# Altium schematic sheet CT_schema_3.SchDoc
size 313 x 200 mm
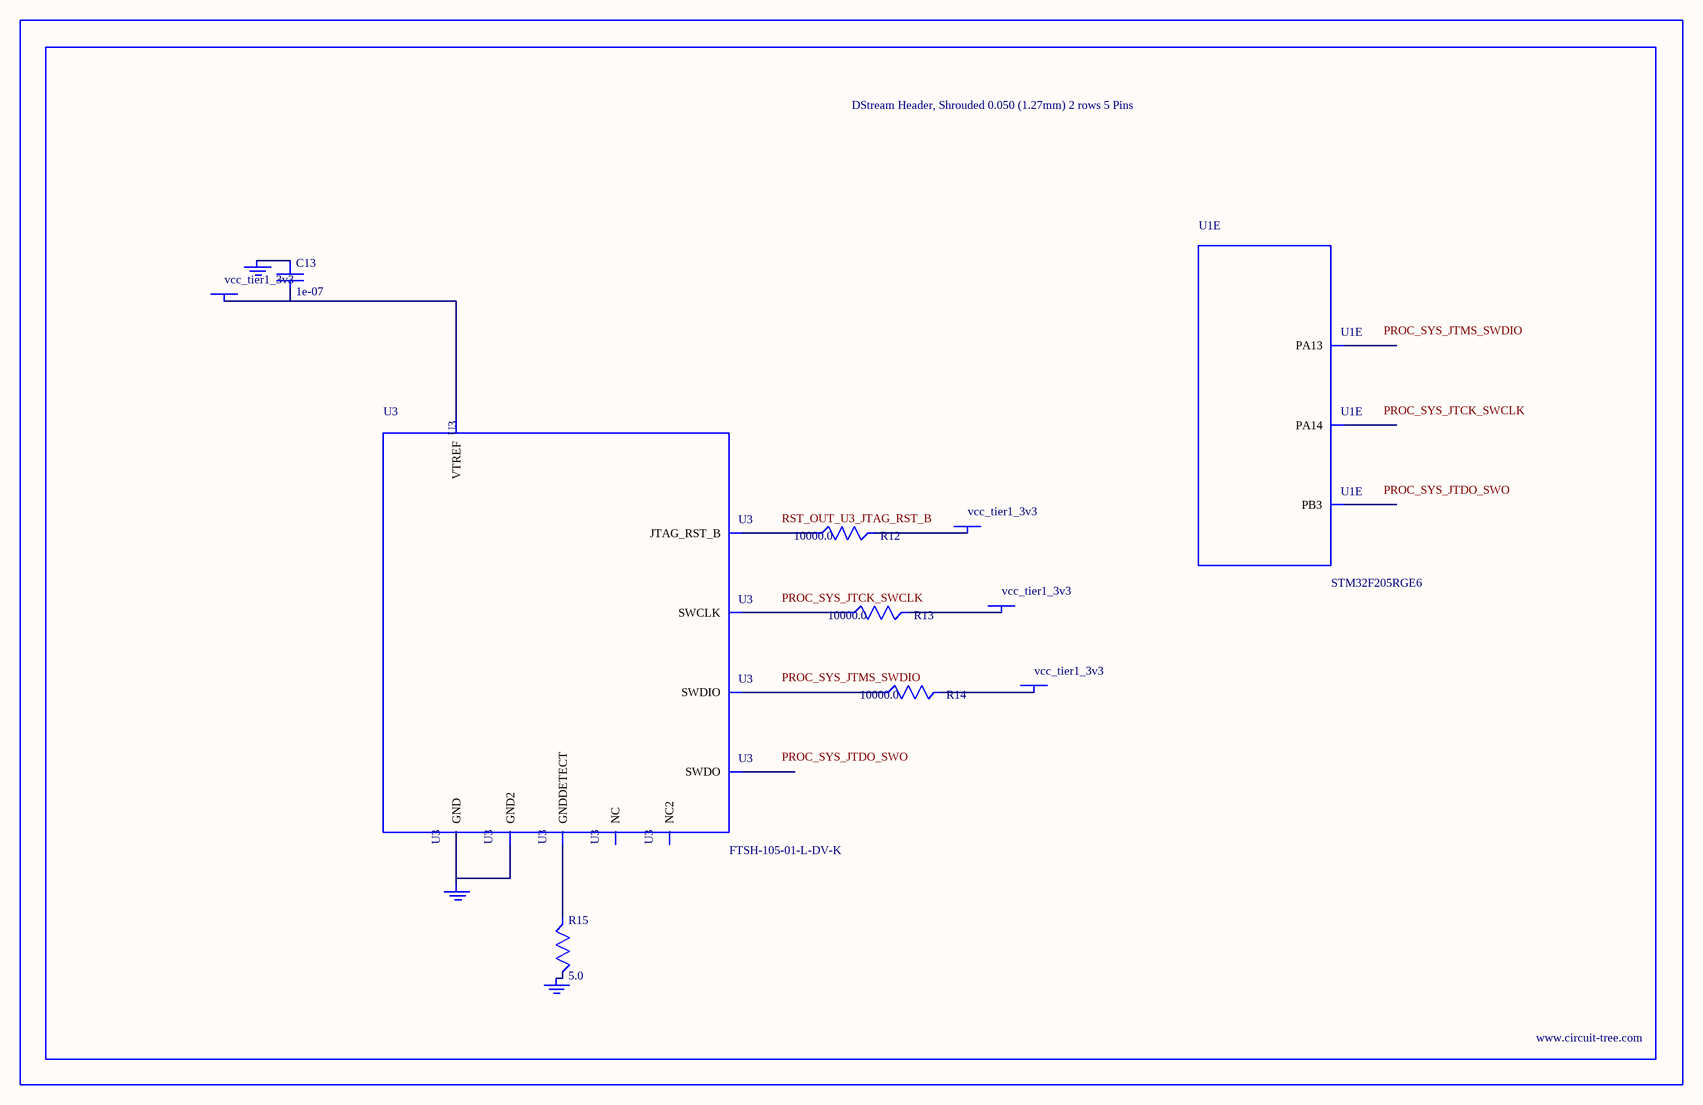
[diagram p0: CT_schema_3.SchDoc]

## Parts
BORDER2  (no value)
C13  1e-07  [C0402]
GND_INSTANCE_2_0  (no value)
GND_INSTANCE_2_1  (no value)
GND_INSTANCE_2_2  (no value)
POWER_INSTANCE_2_0  vcc_tier1_3v3
POWER_INSTANCE_2_1  vcc_tier1_3v3
POWER_INSTANCE_2_2  vcc_tier1_3v3
POWER_INSTANCE_2_3  vcc_tier1_3v3
R12  10000.0  [R0603]
R13  10000.0  [R0603]
R14  10000.0  [R0603]
R15  5.0  [R0603]
U1  STM32F205RGE6  [EWLCSP66]  (part E of 7)
U3  FTSH-105-01-L-DV-K  [SAMTEC_FTSH-105-01-L-DV-K]

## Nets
NetC13_1: C13.1 GND_INSTANCE_2_0.0(GND)
NetC13_2: C13.2 POWER_INSTANCE_2_0.0(PWR) U3.1(VTREF)
NetGND_INSTANCE_2_1_0: GND_INSTANCE_2_1.0(GND) R15.2
NetGND_INSTANCE_2_2_0: GND_INSTANCE_2_2.0(GND) U3.3(GND) U3.5(GND2)
NetPOWER_INSTANCE_2_1_0: POWER_INSTANCE_2_1.0(PWR) R14.2
NetPOWER_INSTANCE_2_2_0: POWER_INSTANCE_2_2.0(PWR) R13.2
NetPOWER_INSTANCE_2_3_0: POWER_INSTANCE_2_3.0(PWR) R12.2
NetR12_1: R12.1 U3.10(JTAG_RST_B)
NetR13_1: R13.1 U3.4(SWCLK)
NetR14_1: R14.1 U3.2(SWDIO)
NetR15_1: R15.1 U3.9(GNDDETECT)

Not connected (* = marked no-connect by the designer): U1 A1(PA14) A4(PB3) B2(PA13); U3 6(SWDO) 7(NC) 8(NC2)

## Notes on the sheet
- Labels drawn without touching a wire or pin: PROC_SYS_JTCK_SWCLK, PROC_SYS_JTDO_SWO, PROC_SYS_JTMS_SWDIO, RST_OUT_U3_JTAG_RST_B

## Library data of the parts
BORDER2 = BORDER_PAGE2
C13 = C0402C104K3RACTU
GND_INSTANCE_2_0-GND_INSTANCE_2_2 = GND
POWER_INSTANCE_2_0-POWER_INSTANCE_2_3 = PWR
R12-R14 = RC0603JR-0710KL
R15 = ERJ-3GEYJ5R1V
